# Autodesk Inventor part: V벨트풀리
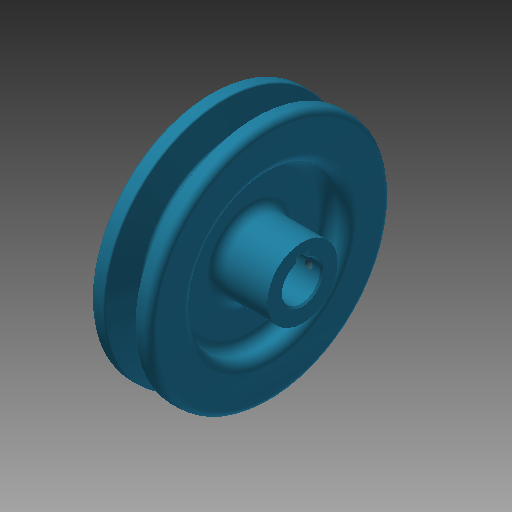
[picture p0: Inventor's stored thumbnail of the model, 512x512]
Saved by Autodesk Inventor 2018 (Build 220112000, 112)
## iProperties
Created: 2015-11
Part Number: V벨트풀리
Material: 강철, 탄소
Document SubType Name: Modeling
Designer: mduedu
Density: 1 g/cm^3
Appearance: 터키옥색
Author: mduedu
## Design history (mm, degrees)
sketch "스케치1"
  geometry: L1 (-9.5, 0)-(9.5, 0); L2 (0, 0)-(0, 37.7); L3 (-4.825, 37.7)-(-9.5, 37.7); L4 (-9.5, 37.7)-(-9.5, 0); L5 (0, 28.7)-(-2.074, 28.7); L6 (-2.074, 28.7)-(-4.825, 37.7); L7 (4.825, 37.7)-(9.5, 37.7); L8 (9.5, 37.7)-(9.5, 0); L9 (0, 28.7)-(2.074, 28.7); L10 (2.074, 28.7)-(4.825, 37.7); L11 (-9.5, 35)-(9.5, 35); 3 further points
  constraints: 22 end point, 7 point on line, 4 perpendicular, 3 symmetric about line, 1 coincident, 1 horizontal, 1 horizontal alignment, 1 midpoint, 1 vertical
  dimensions: "d0" = 19 distance of L1.start L1.end; "d2" = 75.4 diameter of L2.end L1 (derived); "d3" = 34 deg angle of L10 L6; "d4" = 6.3 distance between parallel lines of L11 L9; "d5" = 2.7 distance between parallel lines of L7 L11; "d6" = 8 distance of point (4, 35) point (-4, 35); "d7" = 70 diameter of L11 L1
revolve "회전1" sketch "스케치1" stored, may be unused: angle "d8" = 90 deg
sketch "스케치2"
  geometry: C1 r 24 at (0, 0); C2 r 11 at (0, 0); 1 further point
  constraints: 2 centre point, 2 coincident
  dimensions: "d9" = 48 diameter of C1; "d10" = 22 diameter of C2
extrude "돌출1" cut sketch "스케치2" distance "d11" = 6; taper "d12" = 0 deg
extrude "돌출3" join sketch "스케치2" distance "d37" = 10; taper "d38" = 0 deg
fillet "모깎기1" dims "d13" = 3
fillet "모깎기2" dims "d14" = 3
fillet "모깎기3" dims "d15" = 1, "d16" = 0.5, "d17" = 2
hole "구멍1" diameter "d20" = 12; stored, may be unused: countersink angle "d24" = 90 deg, drill point angle "d26" = 118 deg; dims "d21" = 6, "d22" = 4, "d23" = 2, "d25" = 8, "d39" = 10, "d40" = 10
sketch "스케치3"
  geometry: L1 (-2, 0)-(2, 0); L2 (2, 0)-(2, 7.8); L3 (2, 7.8)-(-2, 7.8); L4 (-2, 7.8)-(-2, 0); 2 further points
  constraints: 8 end point, 2 parallel, 1 coincident, 1 horizontal, 1 midpoint, 1 perpendicular
  dimensions: "d27" = 4 distance of L2.end L3.end; "d29" = 7.8 distance of L3.end L1.start
extrude "돌출2" cut sketch "스케치3" extent not by distance; stored distance "d30" = 6; taper "d31" = 0 deg
chamfer "모따기1" distance "d32" = 0.5; stored, may be unused: second distance "d33" = 2, angle "d34" = 45 deg
node "작업 평면1"
sketch "스케치4"
  geometry: L1 (-19, 11)-(-19, -11) reference; 2 further points
  constraints: 1 horizontal alignment
  dimensions: "d41" = 25 distance from line of point (6, 0) L1
hole "구멍2" sketch "스케치4" at (6, 0) diameter "d42" = 2.459; stored, may be unused: countersink angle "d46" = 90 deg, drill point angle "d48" = 118 deg; dims "d43" = 6, "d44" = 4, "d45" = 2, "d47" = 8
node "솔리드1"
mirror "대칭1"
